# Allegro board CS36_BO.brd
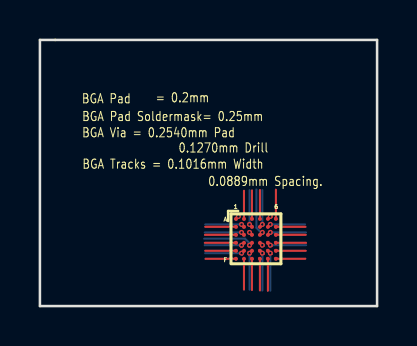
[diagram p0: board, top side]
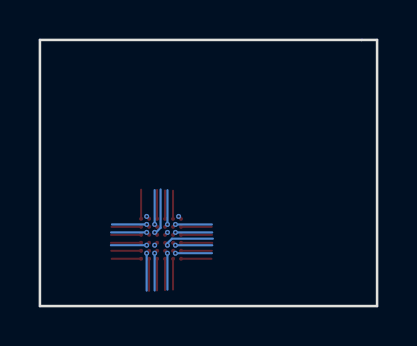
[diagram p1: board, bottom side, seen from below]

Outline 16.89 x 13.33 mm; copper layers: TOP, POWER, GND, BOTTOM. Coordinates in mm from the lower left corner of the outline.
Outline path: 0,13.33 16.89,13.33 16.89,0 0,0 0,13.33

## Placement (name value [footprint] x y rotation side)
U1  -  [ICE65L01-CS36]  10.82 3.37 0 top

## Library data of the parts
U1 = ICE65L01-CS36

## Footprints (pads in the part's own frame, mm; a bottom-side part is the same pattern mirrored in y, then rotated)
ICE65L01-CS36
  round 0.2 smd: A1(-1,1) A2(-0.6,1) A3(-0.2,1) A4(0.2,1) A5(0.6,1) A6(1,1) B1(-1,0.6) B2(-0.6,0.6) B3(-0.2,0.6) B4(0.2,0.6) B5(0.6,0.6) B6(1,0.6) C1(-1,0.2) C2(-0.6,0.2) C3(-0.2,0.2) C4(0.2,0.2) C5(0.6,0.2) C6(1,0.2) D1(-1,-0.2) D2(-0.6,-0.2) D3(-0.2,-0.2) D4(0.2,-0.2) D5(0.6,-0.2) D6(1,-0.2) E1(-1,-0.6) E2(-0.6,-0.6) E3(-0.2,-0.6) E4(0.2,-0.6) E5(0.6,-0.6) E6(1,-0.6) F1(-1,-1) F2(-0.6,-1) F3(-0.2,-1) F4(0.2,-1) F5(0.6,-1) F6(1,-1)

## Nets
GND: U1.C3 U1.D4
VCC: U1.A5
A2: U1.A2
A3: U1.A3
A4: U1.A4
A6: U1.A6
B1: U1.B1
B2: U1.B2
B3: U1.B3
B4: U1.B4
B5: U1.B5
B6: U1.B6
C1: U1.C1
C2: U1.C2
C4: U1.C4
C5: U1.C5
C6: U1.C6
D1: U1.D1
D2: U1.D2
D3: U1.D3
D5: U1.D5
D6: U1.D6
E1: U1.E1
E2: U1.E2
E3: U1.E3
E4: U1.E4
E5: U1.E5
E6: U1.E6
F1: U1.F1
F2: U1.F2
F3: U1.F3
F4: U1.F4
F5: U1.F5
F6: U1.F6
VPP2V5: U1.A1

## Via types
v1: diameter 0.254, hole 0.127, TOP to BOTTOM, 18 vias

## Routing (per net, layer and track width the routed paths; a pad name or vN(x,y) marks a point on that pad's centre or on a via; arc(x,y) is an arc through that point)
GND: length 0.3
  TOP w0.102: U1.C3 10.5,3.69 v1(10.5,3.69) ; U1.D4 11.14,3.05 v1(11.14,3.05)
VCC: length 0.2
  TOP w0.102: v1(11.54,4.49) 11.54,4.49 U1.A5
A2: length 1.4
  TOP w0.102: U1.A2 10.22,5.78
A3: length 1.4
  TOP w0.102: U1.A3 10.62,5.8
A4: length 1.4
  TOP w0.102: U1.A4 11.02,5.82
A6: length 1.5
  TOP w0.102: U1.A6 11.82,5.83
B1: length 1.5
  TOP w0.102: U1.B1 8.29,3.97
B2: length 2
  TOP w0.102: U1.B2 10.1,4.09 v1(10.1,4.09)
  BOTTOM w0.102: v1(10.1,4.09) 8.28,4.09
B3: length 1.9
  TOP w0.102: v1(10.5,4.09) 10.5,4.09 U1.B3
  BOTTOM w0.102: v1(10.5,4.09) 10.5,5.81
B4: length 1.9
  TOP w0.102: v1(11.14,4.09) 11.14,4.09 U1.B4
  BOTTOM w0.102: v1(11.14,4.09) 11.14,5.81
B5: length 1.9
  TOP w0.102: v1(11.54,4.09) 11.54,4.09 U1.B5
  BOTTOM w0.102: v1(11.54,4.09) 13.28,4.09
B6: length 1.5
  TOP w0.102: U1.B6 13.3,3.97
C1: length 1.6
  TOP w0.102: U1.C1 8.27,3.57
C2: length 2
  TOP w0.102: v1(10.1,3.69) 10.1,3.69 U1.C2
  BOTTOM w0.102: v1(10.1,3.69) 8.26,3.69
C4: length 2.5
  TOP w0.102: v1(11.14,3.69) 11.14,3.69 U1.C4
  BOTTOM w0.102: 10.85,5.84 10.85,3.92 11.07,3.69 v1(11.14,3.69)
C5: length 2
  TOP w0.102: v1(11.54,3.69) 11.54,3.69 U1.C5
  BOTTOM w0.102: v1(11.54,3.69) 13.33,3.69
C6: length 1.5
  TOP w0.102: U1.C6 13.32,3.57
D1: length 1.6
  TOP w0.102: U1.D1 8.26,3.17
D2: length 2
  TOP w0.102: v1(10.1,3.05) 10.1,3.05 U1.D2
  BOTTOM w0.102: v1(10.1,3.05) 8.26,3.05
D3: length 2.6
  TOP w0.102: U1.D3 10.5,3.05 v1(10.5,3.05)
  BOTTOM w0.102: v1(10.5,3.05) 10.5,3.15 10.27,3.38 8.23,3.38
D5: length 2
  TOP w0.102: v1(11.54,3.05) 11.54,3.05 U1.D5
  BOTTOM w0.102: v1(11.54,3.05) 13.34,3.05
D6: length 1.5
  TOP w0.102: U1.D6 13.33,3.17
E1: length 1.5
  TOP w0.102: U1.E1 8.28,2.77
E2: length 2
  TOP w0.102: U1.E2 10.1,2.65 v1(10.1,2.65)
  BOTTOM w0.102: v1(10.1,2.65) 8.27,2.65
E3: length 2
  TOP w0.102: U1.E3 10.5,2.65 v1(10.5,2.65)
  BOTTOM w0.102: v1(10.5,2.65) 10.5,0.83
E4: length 2
  TOP w0.102: v1(11.14,2.65) 11.14,2.65 U1.E4
  BOTTOM w0.102: v1(11.14,2.65) 11.14,0.78
E5: length 2
  TOP w0.102: v1(11.54,2.65) 11.54,2.65 U1.E5
  BOTTOM w0.102: v1(11.54,2.65) 11.54,0.77
E6: length 1.5
  TOP w0.102: U1.E6 13.31,2.77
F1: length 1.5
  TOP w0.102: U1.F1 8.3,2.37
F2: length 1.5
  TOP w0.102: U1.F2 10.22,0.83
F3: length 1.6
  TOP w0.102: U1.F3 10.62,0.81
F4: length 1.6
  TOP w0.102: U1.F4 11.02,0.79
F5: length 1.6
  TOP w0.102: U1.F5 11.42,0.77
F6: length 1.5
  TOP w0.102: U1.F6 13.29,2.37
VPP2V5: length 0.2
  TOP w0.102: U1.A1 9.94,4.49 v1(9.94,4.49)

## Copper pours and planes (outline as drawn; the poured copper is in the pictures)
GND on GND: 12.12,4.65 12.12,2.08 9.55,2.08 9.55,4.65
VCC on POWER: 10.9,4.65 12.12,4.65 12.12,2.08 10.9,2.08
VPP2V5 on POWER: 9.55,4.65 10.79,4.65 10.79,2.08 9.55,2.08

Small or netless copper shapes (teardrops, artwork), in the pictures only: 1 on TOP

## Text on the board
Ref Des/Silkscreen Top: A | F | 1 | 6 | BGA Pad | BGA Pad Soldermask= 0.25mm | BGA Via = 0.2540mm Pad | BGA Tracks = 0.1016mm Width | = 0.2mm | 0.1270mm Drill | 0.0889mm Spacing.
